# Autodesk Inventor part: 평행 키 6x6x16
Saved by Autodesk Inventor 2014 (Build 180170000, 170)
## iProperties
Created: 2026-04
Part Number: 평행 키 6x6x16
Material: 강철, 연강
Document SubType Name: Modeling
Designer: dg
Density: 7.86 g/cm^3
Appearance: 강철
Author: jhkim
Description: 키 및 해당 키홈
Creation Date: 2026-03-27
Sending System: Autodesk Inventor 2026
Preprocessor: ST-DEVELOPER v20.1
Author: dg
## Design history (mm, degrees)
node "평행 키 6x6x161"
body "Solid1"
node "기준1"
